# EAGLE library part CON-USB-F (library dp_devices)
USB Female connector
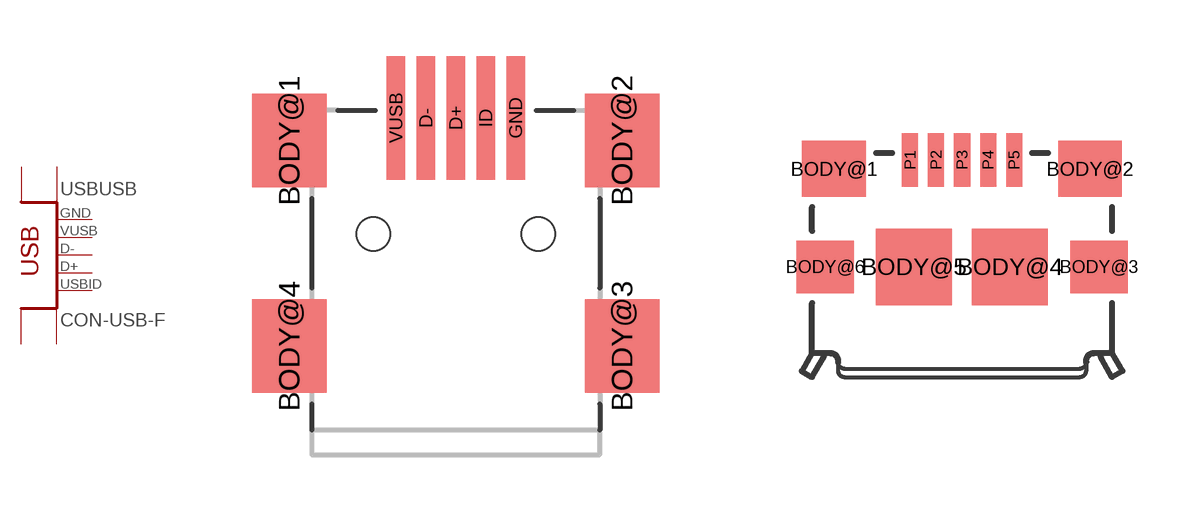
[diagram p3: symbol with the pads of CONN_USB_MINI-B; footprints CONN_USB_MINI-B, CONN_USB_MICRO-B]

Designator prefix USB; gates USB=CONN_USB BODY=USB_BODY_PINS

## CON-USB-F-MINI-B  [CONN_USB_MINI-B]
BODY@1  BODY:BODY  hiz
BODY@2  BODY:BODY  hiz
BODY@3  BODY:BODY  hiz
BODY@4  BODY:BODY  hiz
D+  USB:D+
D-  USB:D-
GND  USB:GND
ID  USB:USBID
VUSB  USB:VUSB

## CON-USB-F-MICRO-B  [CONN_USB_MICRO-B]
BODY@1  BODY:BODY  hiz
BODY@2  BODY:BODY  hiz
BODY@3  BODY:BODY  hiz
BODY@4  BODY:BODY  hiz
P1  USB:VUSB
P2  USB:D-
P3  USB:D+
P4  USB:USBID
P5  USB:GND

## Footprint CONN_USB_MINI-B (pad centres in mm)
USB mini-b connector SMT 0.8 mm pitch adjusted pad dimesion (0.5 x 3.3 mm) on pin 1 to 5
smd 2 x 2.5: BODY@1 -4.45,2.5; BODY@2 4.45,2.5; BODY@3 4.45,-3; BODY@4 -4.45,-3
smd 0.5 x 3.3: D+ 0,3.1; D- -0.8,3.1; GND 1.6,3.1; ID 0.8,3.1; VUSB -1.6,3.1
hole 0.9 at -2.2,0
hole 0.9 at 2.2,0

## Footprint CONN_USB_MICRO-B (pad centres in mm)
USB micro-b connector SMT 0.65 mm pitch, 1.45mm from center to PCB edge, Based on TE part number 1981568-1
smd 1.6 x 1.4: BODY@1 -3.2,2.45; BODY@2 3.2,2.45
smd 1.45 x 1.3: BODY@3 3.425,0; BODY@6 -3.425,0
smd 1.9 x 1.9: BODY@4 1.2,0; BODY@5 -1.2,0
smd 0.4 x 1.35: P1 -1.3,2.675; P2 -0.65,2.675; P3 0,2.675; P4 0.65,2.675; P5 1.3,2.675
